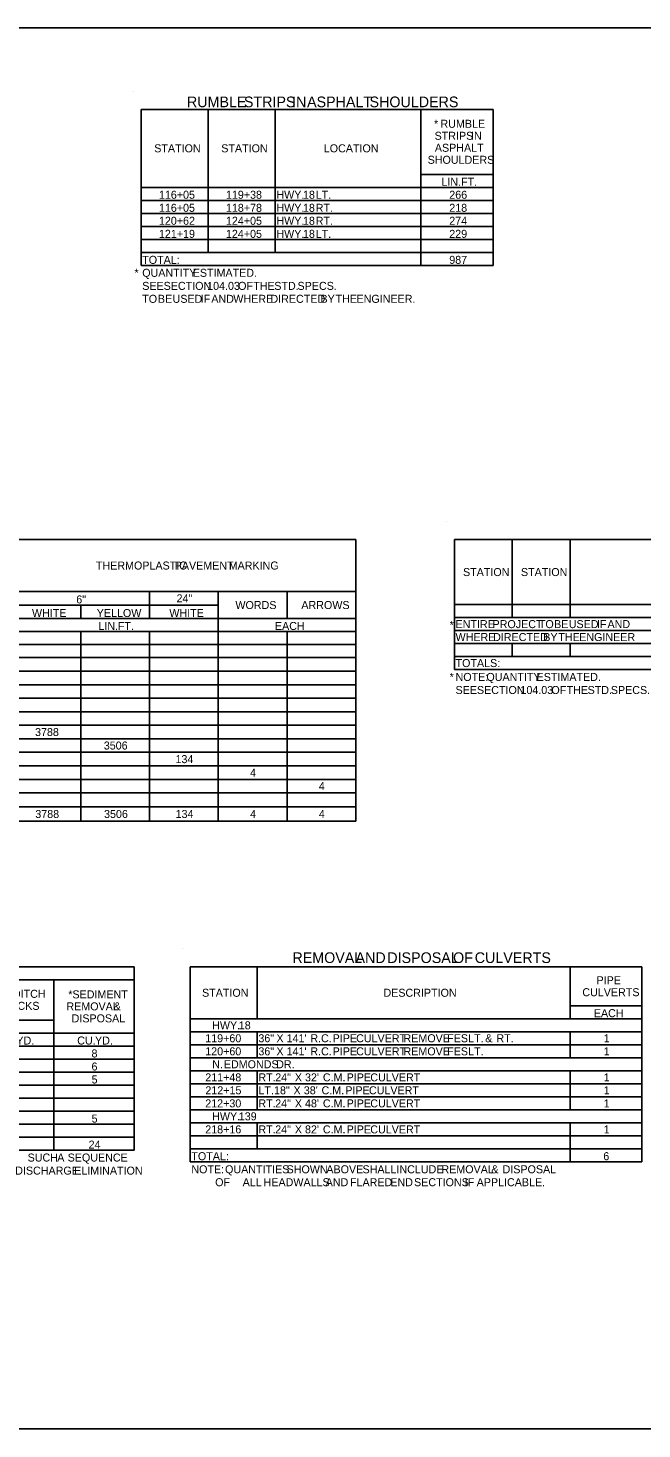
# Model space of a CAD drawing. Extents: x 3289 to 10164, y -1238 to -188.
# Drawn here: x 4170 to 4630, y -1238 to -188 of the extents above; entities that cross this region are included whole.
import ezdxf

# ---------------------------------------------------------------- set-up
doc = ezdxf.new("R2010")
doc.units = 0
for name, color, linetype in [('Default', 7, 'Continuous'), ('DSN_DRFT_Common-Annotations', 7, 'Continuous'), ('DSN_DRFT_Common-Line', 7, 'Continuous'), ('DSN_DRFT_Named-Boundary', 7, 'Continuous'), ('DSN_QNTY_Annotation', 7, 'Continuous')]:
    doc.layers.add(name, color=color, linetype=linetype)

msp = doc.modelspace()

# ---------------------------------------------------------------- linework, layer by layer
at = {"layer": 'DSN_DRFT_Common-Line'}
for p, q in [((4254.9, -248.7), (4518.6, -248.7)), ((4254.9, -365.7), (4254.9, -248.7)), ((4254.9, -365.7), (4254.9, -248.7)), ((4305.1, -355.9), (4305.1, -248.7)), ((4355.3, -355.9), (4355.3, -248.7)), ((4355.3, -355.9), (4355.3, -248.7)), ((4464.5, -365.7), (4464.5, -248.7)), ((4518.6, -365.7), (4518.6, -248.7)), ((4518.6, -365.7), (4518.6, -248.7)), ((4464.5, -297.4), (4518.6, -297.4)), ((4254.9, -307.2), (4518.6, -307.2)), ((4254.9, -307.2), (4518.6, -307.2)), ((4305.1, -355.9), (4305.1, -307.2)), ((4254.9, -316.9), (4518.6, -316.9)), ((4254.9, -326.7), (4518.6, -326.7)), ((4254.9, -336.4), (4518.6, -336.4)), ((4254.9, -346.2), (4518.6, -346.2)), ((4254.9, -355.9), (4464.5, -355.9)), ((4254.9, -355.9), (4355.3, -355.9)), ((4355.3, -355.9), (4518.6, -355.9)), ((4254.9, -365.7), (4518.6, -365.7)), ((4489.6, -571.1), (4868.4, -571.1)), ((4489.6, -668.6), (4489.6, -571.1)), ((4489.6, -668.6), (4489.6, -571.1)), ((4533, -629.6), (4533, -571.1)), ((4576.3, -629.6), (4576.3, -571.1)), ((4489.6, -619.8), (4868.4, -619.8)), ((4489.6, -629.6), (4868.4, -629.6)), ((4533, -629.6), (4533, -619.8)), ((4576.3, -619.8), (4732.3, -619.8)), ((4576.3, -629.6), (4576.3, -619.8)), ((4489.6, -639.3), (4868.4, -639.3)), ((4489.6, -649.1), (4868.4, -649.1)), ((4533, -658.8), (4533, -649.1)), ((4533, -658.8), (4533, -649.1)), ((4576.3, -658.8), (4576.3, -649.1)), ((4576.3, -658.8), (4576.3, -649.1)), ((4489.6, -658.8), (4868.4, -658.8)), ((4489.6, -668.6), (4868.4, -668.6))]:
    msp.add_line(p, q, dxfattribs=at)
at = {"layer": 'DSN_DRFT_Named-Boundary'}
for p, q in [((4249, -235), (4249, -235)), ((4483.7, -557.4), (4483.7, -557.4)), ((4285.8, -877.6), (4285.8, -877.6))]:
    msp.add_line(p, q, dxfattribs=at)
msp.add_lwpolyline([(3288.6, -1237.7), (4913.6, -1237.7), (4913.6, -187.7), (3288.6, -187.7)], close=True, dxfattribs=at)
at = {"layer": 'DSN_QNTY_Annotation'}
for p, q in [((3344.4, -571.1), (4415.8, -571.1)), ((4415.8, -782.1), (4415.8, -571.1)), ((4415.8, -782.1), (4415.8, -571.1)), ((3985.2, -610.1), (4415.8, -610.1)), ((4261.3, -630.4), (4261.3, -610.1)), ((4261.3, -630.4), (4261.3, -610.1)), ((4312.8, -782.1), (4312.8, -610.1)), ((4364.3, -630.4), (4364.3, -610.1)), ((3985.2, -620.2), (4312.8, -620.2)), ((4209.8, -630.4), (4209.8, -620.2)), ((4261.3, -620.2), (4312.8, -620.2)), ((3344.4, -640.1), (4415.8, -640.1)), ((3592.5, -630.4), (4415.8, -630.4)), ((4209.8, -782.1), (4209.8, -640.1)), ((4209.8, -782.1), (4209.8, -640.1)), ((4261.3, -782.1), (4261.3, -640.1)), ((4261.3, -782.1), (4261.3, -640.1)), ((4312.8, -630.4), (4415.8, -630.4)), ((4312.8, -782.1), (4312.8, -640.1)), ((4364.3, -782.1), (4364.3, -640.1)), ((4364.3, -782.1), (4364.3, -640.1)), ((3344.4, -649.9), (4415.8, -649.9)), ((3344.4, -659.6), (4415.8, -659.6)), ((3344.4, -669.8), (4415.8, -669.8)), ((3344.4, -679.9), (4415.8, -679.9)), ((3344.4, -690), (4415.8, -690)), ((3344.4, -700.2), (4415.8, -700.2)), ((3344.4, -710.3), (4415.8, -710.3)), ((3344.4, -720.5), (4415.8, -720.5)), ((3344.4, -730.6), (4415.8, -730.6)), ((3344.4, -740.7), (4415.8, -740.7)), ((3344.4, -750.9), (4415.8, -750.9)), ((3344.4, -761), (4415.8, -761)), ((3344.4, -771.5), (4415.8, -771.5)), ((3344.4, -782.1), (4415.8, -782.1)), ((3344.4, -891.3), (4249.7, -891.3)), ((4249.7, -1028.8), (4249.7, -891.3)), ((4291.6, -891.3), (4630, -891.3)), ((4291.6, -1037.5), (4291.6, -891.3)), ((4291.6, -1037.5), (4291.6, -891.3)), ((4341.9, -930.3), (4341.9, -891.3)), ((4576.3, -930.3), (4576.3, -891.3)), ((4630, -1037.5), (4630, -891.3)), ((4630, -1037.5), (4630, -891.3)), ((3652, -901), (4249.7, -901)), ((4189.7, -1028.8), (4189.7, -901)), ((4576.3, -920.5), (4630, -920.5)), ((4067.9, -931.3), (4189.7, -931.3)), ((4291.6, -930.3), (4630, -930.3)), ((3652, -941), (4249.7, -941)), ((4189.7, -941), (4249.7, -941)), ((4189.7, -1019), (4189.7, -941)), ((4291.6, -940), (4630, -940)), ((4341.9, -959.5), (4341.9, -940)), ((4341.9, -959.5), (4341.9, -940)), ((4576.3, -959.5), (4576.3, -940)), ((4576.3, -959.5), (4576.3, -940)), ((3344.4, -950.8), (4249.7, -950.8)), ((4249.7, -1019), (4249.7, -950.8)), ((4291.6, -949.8), (4630, -949.8)), ((3344.4, -960.5), (4249.7, -960.5)), ((4291.6, -959.5), (4630, -959.5)), ((4291.6, -959.5), (4630, -959.5)), ((3344.4, -970.3), (4249.7, -970.3)), ((4291.6, -969.3), (4630, -969.3)), ((4341.9, -998.5), (4341.9, -969.3)), ((4341.9, -998.5), (4341.9, -969.3)), ((4576.3, -998.5), (4576.3, -969.3)), ((4576.3, -998.5), (4576.3, -969.3)), ((3344.4, -980), (4249.7, -980)), ((4291.6, -979), (4630, -979)), ((3344.4, -989.8), (4249.7, -989.8)), ((4291.6, -988.8), (4630, -988.8)), ((3344.4, -999.5), (4249.7, -999.5)), ((4291.6, -998.5), (4630, -998.5)), ((3344.4, -1009.3), (4249.7, -1009.3)), ((4291.6, -1008.3), (4630, -1008.3)), ((4291.6, -1018), (4630, -1018)), ((4341.9, -1027.8), (4341.9, -1008.3)), ((4341.9, -1027.8), (4341.9, -1008.3)), ((4576.3, -1037.5), (4576.3, -1008.3)), ((4576.3, -1037.5), (4576.3, -1008.3)), ((3344.4, -1019), (4249.7, -1019)), ((3344.4, -1028.8), (4249.7, -1028.8)), ((3967.4, -1019), (4249.7, -1019)), ((4291.6, -1027.8), (4630, -1027.8)), ((4291.6, -1037.5), (4630, -1037.5))]:
    msp.add_line(p, q, dxfattribs=at)

# ---------------------------------------------------------------- texts
at = {"layer": 'Default'}
for s, height, p in [('THERMOPLASTIC', 6, (4221.1, -593.6)), (' PAVEMENT', 6, (4277.9, -593.6)), (' MARKING', 6, (4318.3, -593.6)), ('6"', 6, (4206.4, -619)), ('24"', 6, (4281.5, -618.2)), ('WORDS', 6, (4325.6, -623.2)), ('ARROWS', 6, (4375, -623.2)), ('WHITE', 6, (4173.2, -629.2)), ('YELLOW', 6, (4221.7, -629.2)), ('WHITE', 6, (4276.1, -629.2)), ('LIN.', 6, (4223, -638.9)), (' FT.', 6, (4235.3, -638.9)), ('EACH', 6, (4355.2, -638.9)), ('3788', 6, (4175.5, -718.4)), ('3506', 6, (4227, -728.5)), ('134', 6, (4280.7, -738.7)), ('4', 6, (4336.6, -748.8)), ('4', 6, (4388.1, -758.9)), ('3788', 6, (4175.7, -779.8)), ('3506', 6, (4227.2, -779.8)), ('134', 6, (4280.8, -779.8)), ('4', 6, (4336.6, -779.8)), ('4', 6, (4388.1, -779.8)), ('REMOVAL', 8, (4368.3, -888.5)), (' AND', 8, (4412.6, -888.5)), (' DISPOSAL', 8, (4436.4, -888.5)), (' OF', 8, (4485.7, -888.5)), (' CULVERTS', 8, (4501.9, -888.5)), ('PIPE', 6, (4596.1, -904.4)), (' DITCH', 6, (4156.7, -914.6)), ('*SEDIMENT', 6, (4200.4, -915)), ('STATION', 6, (4300.6, -913.8)), ('DESCRIPTION', 6, (4436.5, -913.8)), ('CULVERTS', 6, (4585.5, -913.4)), ('CHECKS', 6, (4145.4, -923.6)), ('REMOVAL', 6, (4199, -924)), (' &', 6, (4232.2, -924)), ('EACH', 6, (4594.1, -929.1)), ('DISPOSAL', 6, (4202.9, -933)), ('HWY.', 6, (4308.2, -938.2)), (' 18', 6, (4325.9, -938.2)), ('CU.YD.', 6, (4147.7, -949.6)), ('CU.', 6, (4207.1, -949.6)), (' YD.', 6, (4218.2, -949.6)), ('119+60', 6, (4303, -947.9)), ('36"', 6, (4342.8, -947.9)), (' X', 6, (4354.1, -947.9)), (" 141'", 6, (4361.7, -947.9)), (' R.C.', 6, (4379.5, -947.9)), (' PIPE', 6, (4396.2, -947.9)), (' CULVERT', 6, (4413.8, -947.9)), (' REMOVE', 6, (4449.3, -947.9)), (' FES', 6, (4482, -947.9)), (' LT.', 6, (4497.7, -947.9)), (' &', 6, (4510.5, -947.9)), (' RT.', 6, (4518.9, -947.9)), ('1', 6, (4601.5, -947.9)), ('8', 6, (4217.8, -959.3)), ('120+60', 6, (4303, -957.7)), ('36"', 6, (4342.8, -957.7)), (' X', 6, (4354.1, -957.7)), (" 141'", 6, (4361.7, -957.7)), (' R.C.', 6, (4379.5, -957.7)), (' PIPE', 6, (4396.2, -957.7)), (' CULVERT', 6, (4413.8, -957.7)), (' REMOVE', 6, (4449.3, -957.7)), (' FES', 6, (4482, -957.7)), (' LT.', 6, (4497.7, -957.7)), ('1', 6, (4601.5, -957.7)), ('6', 6, (4217.8, -969.1)), ('N.', 6, (4308.2, -967.4)), (' EDMONDS', 6, (4314.7, -967.4)), (' DR.', 6, (4353.9, -967.4)), ('5', 6, (4217.9, -978.8)), ('211+48', 6, (4303, -977.2)), ('RT.', 6, (4342.8, -977.2)), (' 24"', 6, (4353.2, -977.2)), (' X', 6, (4367.9, -977.2)), (" 32'", 6, (4375.5, -977.2)), (' C.M.', 6, (4388.9, -977.2)), (' PIPE', 6, (4406.7, -977.2)), (' CULVERT', 6, (4424.4, -977.2)), ('1', 6, (4601.5, -977.2)), ('212+15', 6, (4303.1, -986.9)), ('LT.', 6, (4342.8, -986.9)), (' 18"', 6, (4352.3, -986.9)), (' X', 6, (4366.9, -986.9)), (" 38'", 6, (4374.6, -986.9)), (' C.M.', 6, (4387.9, -986.9)), (' PIPE', 6, (4405.7, -986.9)), (' CULVERT', 6, (4423.4, -986.9)), ('1', 6, (4601.5, -986.9)), ('212+30', 6, (4303, -996.7)), ('RT.', 6, (4342.8, -996.7)), (' 24"', 6, (4353.2, -996.7)), (' X', 6, (4367.9, -996.7)), (" 48'", 6, (4375.5, -996.7)), (' C.M.', 6, (4388.9, -996.7)), (' PIPE', 6, (4406.7, -996.7)), (' CULVERT', 6, (4424.4, -996.7)), ('1', 6, (4601.5, -996.7)), ('5', 6, (4217.9, -1008.1)), ('HWY.', 6, (4308.2, -1006.4)), (' 139', 6, (4325.9, -1006.4)), ('218+16', 6, (4303, -1016.2)), ('RT.', 6, (4342.8, -1016.2)), (' 24"', 6, (4353.2, -1016.2)), (' X', 6, (4367.9, -1016.2)), (" 82'", 6, (4375.5, -1016.2)), (' C.M.', 6, (4388.9, -1016.2)), (' PIPE', 6, (4406.7, -1016.2)), (' CULVERT', 6, (4424.4, -1016.2)), ('1', 6, (4601.5, -1016.2)), ('24', 6, (4215.6, -1027.6)), (' SUCH', 6, (4167.7, -1037.3)), (' A', 6, (4189.9, -1037.3)), (' SEQUENCE', 6, (4197.7, -1037.3)), ('TOTAL:', 6, (4292.6, -1036.3)), ('6', 6, (4601.2, -1036.3)), (' DISCHARGE', 6, (4158.4, -1047.1)), (' ELIMINATION', 6, (4202.6, -1047.1)), ('NOTE:', 6, (4292.6, -1046.1)), ('        OF', 6, (4292.6, -1055.8)), ('  QUANTITIES', 6, (4313.4, -1046.1)), (' ALL', 6, (4328.8, -1055.8)), (' HEADWALLS', 6, (4344.5, -1055.8)), (' SHOWN', 6, (4361.7, -1046.1)), (' AND', 6, (4391, -1055.8)), (' ABOVE', 6, (4391.5, -1046.1)), (' FLARED', 6, (4409.2, -1055.8)), (' SHALL', 6, (4418.6, -1046.1)), (' END', 6, (4439.4, -1055.8)), (' INCLUDE', 6, (4444, -1046.1)), (' SECTIONS', 6, (4457.2, -1055.8)), (' REMOVAL', 6, (4477.7, -1046.1)), (' IF', 6, (4495.2, -1055.8)), (' APPLICABLE.', 6, (4504.1, -1055.8)), (' &', 6, (4515.1, -1046.1)), (' DISPOSAL', 6, (4523.5, -1046.1))]:
    msp.add_text(s, height=height, dxfattribs=at).set_placement(p)
at = {"layer": 'DSN_DRFT_Common-Annotations'}
for s, height, p in [('RUMBLE', 8, (4289.3, -247.1)), (' STRIPS', 8, (4329, -247.1)), (' IN', 8, (4365.1, -247.1)), (' ASPHALT', 8, (4376.3, -247.1)), (' SHOULDERS', 8, (4423.1, -247.1)), ('*', 6, (4474.4, -262.5)), (' RUMBLE', 6, (4477, -262.5)), ('STRIPS', 6, (4474.8, -271.5)), (' IN', 6, (4499.9, -271.5)), ('STATION', 6, (4264.8, -280.9)), ('STATION', 6, (4315, -280.9)), ('LOCATION', 6, (4391.8, -280.9)), ('SHOULDERS', 6, (4469.6, -289.5)), ('ASPHALT', 6, (4475, -280.5)), ('LIN.FT.', 6, (4479.9, -306)), ('116+05', 6, (4268.3, -315.7)), ('119+38', 6, (4318.5, -315.7)), ('HWY.', 6, (4356.3, -315.7)), (' 18', 6, (4374, -315.7)), (' LT.', 6, (4383.5, -315.7)), ('266', 6, (4485.8, -315.7)), ('116+05', 6, (4268.3, -325.5)), ('118+78', 6, (4318.5, -325.5)), ('HWY.', 6, (4356.3, -325.5)), (' 18', 6, (4374, -325.5)), (' RT.', 6, (4383.5, -325.5)), ('218', 6, (4485.8, -325.5)), ('120+62', 6, (4268.3, -335.2)), ('124+05', 6, (4318.5, -335.2)), ('HWY.', 6, (4356.3, -335.2)), (' 18', 6, (4374, -335.2)), (' RT.', 6, (4383.5, -335.2)), ('274', 6, (4485.8, -335.2)), ('121+19', 6, (4268.3, -345)), ('124+05', 6, (4318.5, -345)), ('HWY.', 6, (4356.3, -345)), (' 18', 6, (4374, -345)), (' LT.', 6, (4383.5, -345)), ('229', 6, (4485.8, -345)), ('TOTAL:', 6, (4255.8, -364.5)), ('987', 6, (4485.8, -364.5)), ('*', 6, (4250, -374.2)), ('QUANTITY', 6, (4255.8, -374.2)), ('SEE', 6, (4255.8, -384)), (' SECTION', 6, (4269.6, -384)), (' ESTIMATED.', 6, (4291.4, -374.2)), (' 104.03', 6, (4302.2, -384)), (' OF', 6, (4325.4, -384)), (' THE', 6, (4336.8, -384)), (' STD.', 6, (4352.5, -384)), (' SPECS.', 6, (4369.9, -384)), ('TO', 6, (4255.8, -393.7)), (' BE', 6, (4265.3, -393.7)), (' USED', 6, (4276.3, -393.7)), (' IF', 6, (4297.4, -393.7)), (' AND', 6, (4305.3, -393.7)), (' WHERE', 6, (4321.8, -393.7)), (' DIRECTED', 6, (4349.6, -393.7)), (' BY', 6, (4387.1, -393.7)), (' THE', 6, (4398.4, -393.7)), (' ENGINEER.', 6, (4414.1, -393.7)), ('STATION', 6, (4496.1, -598.5)), ('STATION', 6, (4539.5, -598.5)), ('*', 6, (4486.1, -638.1)), ('ENTIRE', 6, (4490.5, -637.5)), (' PROJECT', 6, (4516, -637.5)), (' TO', 6, (4550.7, -637.5)), (' BE', 6, (4562.1, -637.5)), (' USED', 6, (4573.1, -637.5)), (' IF', 6, (4594.2, -637.5)), (' AND', 6, (4602.1, -637.5)), ('WHERE', 6, (4490.5, -647.2)), (' DIRECTED', 6, (4516.4, -647.2)), (' BY', 6, (4554, -647.2)), (' THE', 6, (4565.3, -647.2)), (' ENGINEER', 6, (4580.9, -647.2)), ('TOTALS:', 6, (4490.5, -666.7)), ('*', 6, (4486.1, -677.1)), ('NOTE:', 6, (4490.5, -677.1)), (' QUANTITY', 6, (4511.4, -677.1)), (' ESTIMATED.', 6, (4549, -677.1)), ('SEE', 6, (4490.5, -686.9)), (' SECTION', 6, (4504.3, -686.9)), (' 104.03', 6, (4536.9, -686.9)), (' OF', 6, (4560.1, -686.9)), (' THE', 6, (4571.5, -686.9)), (' STD.', 6, (4587.2, -686.9)), (' SPECS.', 6, (4604.6, -686.9))]:
    msp.add_text(s, height=height, dxfattribs=at).set_placement(p)

doc.saveas('drawing.dxf')
